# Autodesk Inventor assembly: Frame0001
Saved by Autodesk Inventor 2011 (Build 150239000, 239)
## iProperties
Created: 2020-12
Part Number: Frame0001
Document SubType Name: Assembly
Designer: PC
_FrameDoc: Frame Assembly
_Version: 15.0.0
Author: PC
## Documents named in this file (8)
- C:\Users\PC\Documents\Inventor\workshop-crane-powered-by-drill\3_tubo-telescopico\Frame\Frame0001.iam
- C:\Users\PC\Documents\Inventor\workshop-crane-powered-by-drill\3_tubo-telescopico\Frame\Skeleton0001.ipt
- C:\Users\PC\Documents\Inventor\workshop-crane-powered-by-drill\3_tubo-telescopico\Frame\DIN 45 x 8 00000001.ipt
- DIN 45 x 8 00000001.ipt
- C:\Users\PC\Documents\Inventor\workshop-crane-powered-by-drill\3_tubo-telescopico\Frame\DIN 45 x 8 00000002.ipt
- DIN 45 x 8 00000002.ipt
- C:\Users\PC\Documents\Inventor\workshop-crane-powered-by-drill\3_tubo-telescopico\Frame\DIN 50x50x4 00000003.ipt
- DIN 50x50x4 00000003.ipt
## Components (4 placed, 4 different names)
1. Frame Reference Model
2. DIN 45 x 8 00000001:1
3. DIN 45 x 8 00000002:1
4. DIN 50x50x4 00000003:1
